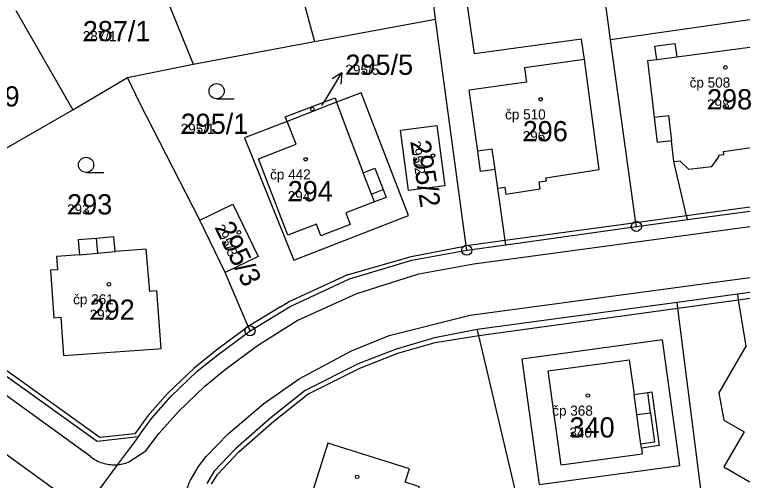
# Model space of a CAD drawing. Extents: x -763628 to -761565, y -976033 to -973833.
# Drawn here: x -762540.9 to -762468.9, y -974773.8 to -974727.8 of the extents above; entities that cross this region are included whole.
import ezdxf

# ---------------------------------------------------------------- set-up
doc = ezdxf.new("R2010")
doc.units = 0
for name, color, linetype in [('KN_cisla parcel 1000', 7, 'Continuous'), ('KN_cisla parcel 500', 7, 'Continuous'), ('KN_cisla parcel znacky', 7, 'Continuous'), ('KN_cisla popisna 500', 7, 'Continuous'), ('KN_hranice parcel', 7, 'Continuous'), ('KN_vnitrni kresba parcel', 7, 'Continuous'), ('KN_znacky bodu BP', 7, 'Continuous'), ('KN_znacky budov', 7, 'Continuous'), ('KN_znacky kultur', 7, 'Continuous')]:
    doc.layers.add(name, color=color, linetype=linetype)

msp = doc.modelspace()

# ---------------------------------------------------------------- linework, layer by layer
at = {"layer": 'KN_cisla parcel znacky'}
for p, q in [((-762510.12, -974736.09), (-762508.574, -974733.518)), ((-762508.574, -974733.518), (-762509.519, -974734.118)), ((-762508.574, -974733.518), (-762508.661, -974734.634)), ((-762510.52, -974736.76), (-762510.12, -974736.09))]:
    msp.add_line(p, q, dxfattribs=at)
at = {"layer": 'KN_hranice parcel'}
for p, q in [((-762531.06, -974713.3), (-762523.27, -974732.68)), ((-762515.55, -974714.5), (-762511.27, -974730.44)), ((-762481.97, -974730.25), (-762483.78, -974717.13)), ((-762540.79, -974727.36), (-762535.17, -974737.18)), ((-762511.27, -974730.44), (-762499.28, -974728.23)), ((-762523.27, -974732.68), (-762511.27, -974730.44)), ((-762529.76, -974733.97), (-762523.27, -974732.68)), ((-762535.17, -974737.18), (-762529.76, -974733.97)), ((-762509.07, -974736.44), (-762513.97, -974738.33)), ((-762543.51, -974741.97), (-762535.17, -974737.18)), ((-762474.38, -974748.02), (-762461.57, -974746.31)), ((-762520.1, -974753.26), (-762522.6, -974748.09)), ((-762479.43, -974748.7), (-762474.38, -974748.02)), ((-762492.33, -974750.52), (-762479.43, -974748.7)), ((-762496.19, -974751.06), (-762492.33, -974750.52)), ((-762455.58, -974753.53), (-762469.44, -974755.41)), ((-762469.44, -974755.41), (-762475.39, -974756.22)), ((-762475.39, -974756.22), (-762495.16, -974758.88))]:
    msp.add_line(p, q, dxfattribs=at)
for points in [[(-762499.28, -974728.23), (-762500.26, -974720.43), (-762501.22, -974714.67)], [(-762492.33, -974750.52), (-762492.39, -974750.1), (-762493.14, -974744.91), (-762492.44, -974744.81), (-762492.33, -974745.51), (-762488.93, -974744.99), (-762489.03, -974744.29), (-762488.33, -974744.19), (-762488.38, -974743.89), (-762483.1, -974743.09), (-762484.57, -974732.19), (-762484.84, -974730.21), (-762495.44, -974731.65), (-762497.12, -974719.95), (-762497.68, -974714.98)], [(-762496.19, -974751.06), (-762496.25, -974750.62), (-762499.28, -974728.23)], [(-762474.38, -974748.02), (-762474.46, -974747.66), (-762475.72, -974742.3), (-762475.09, -974742.22), (-762475.07, -974742.3), (-762474.27, -974743.05), (-762471.96, -974742.77), (-762471.26, -974741.82), (-762471.28, -974741.66), (-762470.79, -974741.59), (-762470.82, -974741.31), (-762465.61, -974740.55), (-762466.92, -974730.8), (-762467.27, -974728.17), (-762481.97, -974730.25)], [(-762479.43, -974748.7), (-762479.48, -974748.34), (-762481.97, -974730.25)], [(-762522.6, -974748.09), (-762528.53, -974736.51), (-762529.76, -974733.97)], [(-762513.97, -974738.33), (-762518.17, -974739.96), (-762513.32, -974752.03), (-762501.98, -974747.64), (-762506.64, -974735.5), (-762509.07, -974736.44)], [(-762513.97, -974738.33), (-762514.15, -974737.87), (-762509.23, -974735.99), (-762509.07, -974736.44)], [(-762501.96, -974745.16), (-762502.76, -974739.2), (-762499.17, -974738.72), (-762498.36, -974744.68), (-762501.96, -974745.16)], [(-762522.6, -974748.09), (-762519.33, -974746.51), (-762516.83, -974751.68), (-762520.1, -974753.26)], [(-762532.81, -974749.89), (-762534.62, -974750.04), (-762534.5, -974751.5), (-762536.77, -974751.69), (-762536.68, -974752.99), (-762537.38, -974753.03), (-762537.04, -974757.74), (-762536.35, -974757.69), (-762536.09, -974761.46), (-762526.77, -974760.79), (-762526.44, -974760.77), (-762526.86, -974755.07), (-762527.55, -974755.13), (-762527.9, -974750.95), (-762530.99, -974751.2), (-762531.11, -974749.75), (-762532.81, -974749.89)], [(-762517.64, -974759.02), (-762514.44, -974757.07), (-762513.68, -974756.61), (-762507.8, -974753.89), (-762501.65, -974752.04), (-762496.19, -974751.06)], [(-762517.64, -974759.02), (-762517.82, -974758.6), (-762520.1, -974753.26)], [(-762553.15, -974755.35), (-762532.76, -974769.94), (-762528.66, -974769.46)], [(-762469.44, -974755.41), (-762469.35, -974755.97), (-762468.59, -974760.54), (-762471.26, -974765.14), (-762470.77, -974767.86), (-762468.77, -974769.01), (-762470.77, -974772.48), (-762465.31, -974775.63), (-762461.28, -974777.95), (-762457.54, -974780.1), (-762457.1, -974783.32), (-762456.16, -974788.68)], [(-762472.64, -974778.04), (-762475.32, -974756.79), (-762475.39, -974756.22)], [(-762528.66, -974769.46), (-762527.37, -974767.68), (-762525.47, -974765.52), (-762522.85, -974763.02), (-762520.83, -974761.4), (-762517.64, -974759.02)], [(-762495.16, -974758.88), (-762499.38, -974759.72), (-762503.19, -974760.83), (-762506.93, -974762.3), (-762512.2, -974764.91), (-762515.55, -974767.59), (-762519.06, -974770.69), (-762521.2, -974772.91), (-762521.9, -974774.11)], [(-762488.73, -974786.15), (-762488.79, -974785.9), (-762495.01, -974759.5), (-762495.16, -974758.88)], [(-762490.74, -974761.83), (-762489.04, -974774.23), (-762475.14, -974772.32), (-762476.86, -974759.93), (-762490.74, -974761.83)], [(-762528.66, -974769.46), (-762530.73, -974772.25), (-762534.71, -974777.62), (-762536.84, -974780.5)], [(-762512.07, -974778.37), (-762511.5, -974778.54), (-762510.64, -974779.23), (-762509.56, -974779.56), (-762508.43, -974779.49), (-762508.02, -974779.62), (-762508.23, -974780.29), (-762504.59, -974781.41), (-762503.13, -974776.68), (-762501.71, -974777.12), (-762500.88, -974774.43), (-762502.29, -974773.99), (-762501.88, -974772.66), (-762509.94, -974770.13), (-762512.04, -974776.8), (-762511.65, -974776.92), (-762512.07, -974778.37)]]:
    msp.add_lwpolyline(points, dxfattribs=at)
at = {"layer": 'KN_vnitrni kresba parcel'}
for p, q in [((-762477.59, -974730.9), (-762475.61, -974730.63)), ((-762477.41, -974732.2), (-762477.59, -974730.9)), ((-762475.61, -974730.63), (-762475.43, -974731.94)), ((-762475.43, -974731.94), (-762466.92, -974730.8)), ((-762484.57, -974732.19), (-762490.5, -974733.02)), ((-762478.3, -974732.32), (-762477.41, -974732.2)), ((-762477.63, -974737.9), (-762478.3, -974732.32)), ((-762477.41, -974732.2), (-762475.43, -974731.94)), ((-762490.5, -974733.02), (-762490.3, -974734.46)), ((-762495.5, -974752.4), (-762353.37, -974733.19)), ((-762490.3, -974734.46), (-762495.95, -974735.25)), ((-762495.11, -974741.26), (-762495.95, -974735.25)), ((-762509.07, -974736.44), (-762508.24, -974738.72)), ((-762477.63, -974737.9), (-762476.25, -974737.74)), ((-762477.33, -974740.4), (-762477.63, -974737.9)), ((-762476.25, -974737.74), (-762475.95, -974740.23)), ((-762513.08, -974740.58), (-762513.97, -974738.33)), ((-762508.24, -974738.72), (-762506.45, -974743.4)), ((-762495.87, -974757.48), (-762356.91, -974738.71)), ((-762475.95, -974740.23), (-762477.33, -974740.4)), ((-762475.72, -974742.3), (-762475.95, -974740.23)), ((-762533.43, -974771.45), (-762576.14, -974740.55)), ((-762516.8, -974742.01), (-762513.08, -974740.58)), ((-762493.68, -974741.06), (-762495.11, -974741.26)), ((-762493.39, -974743.07), (-762493.68, -974741.06)), ((-762494.83, -974743.28), (-762495.11, -974741.26)), ((-762513.9, -974749.57), (-762516.8, -974742.01)), ((-762506.45, -974743.4), (-762505.28, -974742.95)), ((-762505.28, -974742.95), (-762504.47, -974745.06)), ((-762493.39, -974743.07), (-762494.83, -974743.28)), ((-762493.14, -974744.91), (-762493.39, -974743.07)), ((-762505.64, -974745.51), (-762506.45, -974743.4)), ((-762577.8, -974745.14), (-762536.34, -974775.14)), ((-762505.64, -974745.51), (-762504.47, -974745.06)), ((-762504.47, -974745.06), (-762504.17, -974745.84)), ((-762505.34, -974746.28), (-762505.64, -974745.51)), ((-762504.17, -974745.84), (-762505.34, -974746.28)), ((-762461.62, -974745.92), (-762474.46, -974747.66)), ((-762505.34, -974746.28), (-762508.16, -974747.37)), ((-762508.16, -974747.37), (-762507.72, -974748.51)), ((-762474.46, -974747.66), (-762479.48, -974748.34)), ((-762511.06, -974748.48), (-762513.9, -974749.57)), ((-762510.63, -974749.62), (-762511.06, -974748.48)), ((-762507.72, -974748.51), (-762510.63, -974749.62)), ((-762479.48, -974748.34), (-762492.39, -974750.1)), ((-762532.69, -974751.35), (-762532.81, -974749.89)), ((-762492.39, -974750.1), (-762496.25, -974750.62)), ((-762501.69, -974751.67), (-762496.25, -974750.62)), ((-762534.5, -974751.5), (-762532.69, -974751.35)), ((-762532.69, -974751.35), (-762530.99, -974751.2)), ((-762507.99, -974753.48), (-762501.69, -974751.67)), ((-762500.95, -974753.4), (-762495.5, -974752.4)), ((-762507.99, -974753.48), (-762513.86, -974756.2)), ((-762507.06, -974755.34), (-762500.95, -974753.4)), ((-762469.35, -974755.97), (-762455.51, -974754.07)), ((-762532.49, -974769.57), (-762552.88, -974754.98)), ((-762512.96, -974758.01), (-762507.06, -974755.34)), ((-762514.62, -974756.66), (-762513.86, -974756.2)), ((-762475.32, -974756.79), (-762469.35, -974755.97)), ((-762514.62, -974756.66), (-762517.82, -974758.6)), ((-762495.01, -974759.5), (-762475.32, -974756.79)), ((-762503.87, -974759.49), (-762495.87, -974757.48)), ((-762516.9, -974760.48), (-762512.96, -974758.01)), ((-762517.82, -974758.6), (-762521.09, -974761.03)), ((-762507.59, -974761), (-762503.87, -974759.49)), ((-762499.32, -974760.17), (-762495.01, -974759.5)), ((-762520.09, -974762.84), (-762516.9, -974760.48)), ((-762503.02, -974761.24), (-762499.32, -974760.17)), ((-762521.09, -974761.03), (-762523.16, -974762.7)), ((-762512.79, -974763.77), (-762507.59, -974761)), ((-762506.77, -974762.72), (-762503.02, -974761.24)), ((-762488.16, -974762.99), (-762480.13, -974761.89)), ((-762480.13, -974761.89), (-762479.66, -974765.32)), ((-762523.16, -974762.7), (-762525.78, -974765.19)), ((-762522.1, -974764.48), (-762520.09, -974762.84)), ((-762511.92, -974765.27), (-762506.77, -974762.72)), ((-762486.88, -974772.31), (-762488.16, -974762.99)), ((-762516.26, -974766.21), (-762512.79, -974763.77)), ((-762524.72, -974767), (-762522.1, -974764.48)), ((-762525.78, -974765.19), (-762527.74, -974767.42)), ((-762515.27, -974767.95), (-762511.92, -974765.27)), ((-762479.66, -974765.32), (-762478.29, -974765.13)), ((-762479.39, -974767.3), (-762479.66, -974765.32)), ((-762478.29, -974765.13), (-762477.9, -974765.05)), ((-762478.02, -974767.12), (-762478.29, -974765.13)), ((-762477.9, -974765.05), (-762477.16, -974770.37)), ((-762519.81, -974769.21), (-762516.26, -974766.21)), ((-762526.62, -974769.15), (-762524.72, -974767)), ((-762527.74, -974767.42), (-762529.02, -974769.19)), ((-762479.39, -974767.3), (-762478.02, -974767.12)), ((-762478.98, -974770.22), (-762479.39, -974767.3)), ((-762478.02, -974767.12), (-762477.62, -974770.03)), ((-762518.73, -974771), (-762515.27, -974767.95)), ((-762527.93, -974770.88), (-762526.62, -974769.15)), ((-762529.02, -974769.19), (-762532.49, -974769.57)), ((-762521.96, -974771.43), (-762519.81, -974769.21)), ((-762477.62, -974770.03), (-762478.98, -974770.22)), ((-762478.93, -974770.61), (-762478.98, -974770.22)), ((-762477.16, -974770.37), (-762478.93, -974770.61)), ((-762478.93, -974770.61), (-762478.85, -974771.21)), ((-762529.62, -974771.99), (-762527.93, -974770.88)), ((-762520.87, -974773.23), (-762518.73, -974771)), ((-762478.85, -974771.21), (-762486.88, -974772.31)), ((-762522.75, -974772.45), (-762521.96, -974771.43)), ((-762523.34, -974773.45), (-762522.75, -974772.45)), ((-762521.45, -974774.17), (-762520.87, -974773.23))]:
    msp.add_line(p, q, dxfattribs=at)
for points in [[(-762533.43, -974771.45), (-762533.294, -974771.552), (-762533.154, -974771.647), (-762533.01, -974771.737), (-762532.862, -974771.82), (-762532.71, -974771.896), (-762532.556, -974771.965), (-762532.398, -974772.028), (-762532.238, -974772.083), (-762532.075, -974772.131), (-762531.91, -974772.172), (-762531.744, -974772.206), (-762531.576, -974772.232), (-762531.408, -974772.251), (-762531.238, -974772.262), (-762531.069, -974772.265), (-762530.899, -974772.261), (-762530.73, -974772.25)], [(-762530.73, -974772.25), (-762530.568, -974772.232), (-762530.406, -974772.208), (-762530.246, -974772.177), (-762530.087, -974772.14), (-762529.929, -974772.096), (-762529.773, -974772.046), (-762529.62, -974771.99)], [(-762523.98, -974776.89), (-762524.01, -974776.694), (-762524.032, -974776.496), (-762524.047, -974776.298), (-762524.053, -974776.1), (-762524.052, -974775.902), (-762524.043, -974775.703), (-762524.026, -974775.505), (-762524.001, -974775.308), (-762523.969, -974775.113), (-762523.929, -974774.918), (-762523.881, -974774.725), (-762523.825, -974774.535), (-762523.763, -974774.346), (-762523.692, -974774.161), (-762523.615, -974773.978), (-762523.53, -974773.798), (-762523.439, -974773.622), (-762523.34, -974773.45)]]:
    msp.add_lwpolyline(points, dxfattribs=at)
at = {"layer": 'KN_znacky bodu BP'}
for centre, radius in [((-762479.43, -974748.7), 0.5), ((-762479.43, -974748.7), 0.0303), ((-762496.19, -974751.06), 0.5), ((-762496.19, -974751.06), 0.0303), ((-762517.64, -974759.02), 0.5), ((-762517.64, -974759.02), 0.0303)]:
    msp.add_circle(centre, radius, dxfattribs=at)
at = {"layer": 'KN_znacky budov'}
for centre in [(-762470.637, -974732.989), (-762488.887, -974736.139), (-762511.477, -974737.109), (-762499.547, -974741.709), (-762512.127, -974742.069), (-762518.737, -974749.299), (-762531.607, -974754.419), (-762484.227, -974765.419), (-762507.047, -974773.459)]:
    msp.add_circle(centre, 0.175, dxfattribs=at)
at = {"layer": 'KN_znacky kultur'}
for p, q in [((-762520.943, -974736.09), (-762519.193, -974736.09)), ((-762533.853, -974743.37), (-762532.103, -974743.37))]:
    msp.add_line(p, q, dxfattribs=at)
for centre in [(-762520.943, -974735.34), (-762533.853, -974742.62)]:
    msp.add_circle(centre, 0.75, dxfattribs=at)

# ---------------------------------------------------------------- texts
at = {"layer": 'KN_cisla parcel 1000'}
for s, p in [('287/1', (-762534.18, -974730.4)), ('295/5', (-762508.2, -974733.72)), ('289', (-762544.89, -974736.85)), ('298', (-762472.44, -974737.14)), ('295/1', (-762524.5, -974739.56)), ('296', (-762490.67, -974740.29)), ('294', (-762513.91, -974746.22)), ('293', (-762535.73, -974747.52)), ('292', (-762533.5, -974757.93)), ('340', (-762486.04, -974769.57))]:
    msp.add_text(s, height=2, dxfattribs=at).set_placement(p)
for s, rotation, p in [('295/2', 279, (-762501.794, -974740.329)), ('295/3', 296, (-762521.163, -974748.811))]:
    msp.add_text(s, height=2, rotation=rotation, dxfattribs=at).set_placement(p)
at = {"layer": 'KN_cisla parcel 500'}
for s, p in [('287/1', (-762534.18, -974730.4)), ('295/5', (-762508.2, -974733.72)), ('298', (-762472.44, -974737.14)), ('295/1', (-762524.5, -974739.56)), ('296', (-762490.67, -974740.29)), ('294', (-762513.91, -974746.22)), ('293', (-762535.73, -974747.52)), ('292', (-762533.5, -974757.93)), ('340', (-762486.04, -974769.57))]:
    msp.add_text(s, height=1, dxfattribs=at).set_placement(p)
for s, rotation, p in [('295/2', 279, (-762501.794, -974740.329)), ('295/3', 296, (-762521.163, -974748.811))]:
    msp.add_text(s, height=1, rotation=rotation, dxfattribs=at).set_placement(p)
at = {"layer": 'KN_cisla popisna 500'}
for s, p in [('čp 508', (-762474.161, -974734.981)), ('čp 510', (-762492.411, -974738.131)), ('čp 442', (-762515.651, -974744.061)), ('čp 361', (-762535.131, -974756.411)), ('čp 368', (-762487.751, -974767.411))]:
    msp.add_text(s, height=1, dxfattribs=at).set_placement(p)

doc.saveas('drawing.dxf')
